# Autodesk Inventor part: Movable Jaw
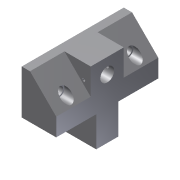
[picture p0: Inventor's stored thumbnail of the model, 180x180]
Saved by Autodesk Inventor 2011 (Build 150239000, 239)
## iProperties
Shininess: 77.0
Length Units: 11269
Angle Units: 11279
Time Units: 11290
Mass Units: 11283
Length Display Precision: 3
Angle Display Precision: 2
Created: 2002-02
Part Number: Movable Jaw
Document SubType Name: Modeling
Designer: ***
Density: 1 g/cm^3
Density: 0.0
Volumn: 0.0
Area: 0.0
PropertySet Name: Model Information
Control State: 0
Master: False
Checked Out: False
Author: ***
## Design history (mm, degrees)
sketch "Sketch2"
  geometry: L1 (2.39, 41.509)-(2.39, 9.509); L2 (2.39, 9.509)-(-22.61, 9.509); L3 (-22.61, 9.509)-(-22.61, 22.509); L4 (-22.61, 22.509)-(-3.61, 41.509); L5 (-3.61, 41.509)-(2.39, 41.509)
  constraints: 10 end point, 2 parallel, 1 perpendicular, 1 vertical
  dimensions: "d0" = 25 distance of L1.end L2.end; "d2" = 13 distance of L2.end L3.end; "d3" = 32 distance between parallel lines of L5 L2; "d4" = 6 distance of L4.end L1.start
extrude "Extrusion1" new body sketch "Sketch2" stored distance "d5" = 74; taper "d6" = 0 deg
sketch "Sketch3"
  geometry: L1 (-19, 25)-(11, 25); L2 (11, 25)-(11, 49); L3 (11, 49)-(-19, 49); L4 (-19, 49)-(-19, 25); L5 (0, 0)-(13, 0) reference; L6 (-19, 74)-(-19, 0) reference; L7 (11.924, 29)-(35, 29); L8 (35, 29)-(35, 45); L9 (35, 45)-(11.924, 45); L10 (11.924, 45)-(11.924, 29); L11 (13, 74)-(13, 0) reference
  constraints: 16 end point, 4 parallel, 2 horizontal, 2 perpendicular, 1 collinear
  dimensions: "d7" = 24 distance of L3.end L1.start; "d8" = 30 distance of L1.start L1.end; "d9" = 25 distance between parallel lines of L5 L1; "d10" = 16 distance of L7.end L8.end; "d11" = 4 distance between parallel lines of L3 L9; "d12" = 22 distance between parallel lines of L11 L8
extrude "Extrusion2" join sketch "Sketch3" distance "d13" = 25; taper "d14" = 0 deg
sketch "Sketch4"
  geometry: L1 (-19, -25)-(-19, -49) reference; L2 (-19, -49)-(0, -49) reference; 1 further point
  dimensions: "d15" = 11 distance from line of L1 point (-8, -37); "d16" = 12 distance from line of L2 point (-8, -37)
hole "Hole1" sketch "Sketch4" at (-8, -37) diameter "d17" = 10; stored, may be unused: countersink angle "d21" = 82 deg, drill point angle "d23" = 0 deg; dims "d18" = 6, "d19" = 4, "d20" = 2, "d22" = 13
sketch "Sketch5"
  geometry: L1 (-19, -49)-(-19, -74) reference; L2 (0, -74)-(13, -74) reference; 1 further point
  dimensions: "d24" = 14 distance from line of L1 point (-5, -62); "d25" = 12 distance from line of L2 point (-5, -62)
hole "Hole2" sketch "Sketch5" at (-5, -62) diameter "d26" = 6; stored, may be unused: countersink angle "d30" = 82 deg, drill point angle "d32" = 0 deg; dims "d27" = 6, "d28" = 8, "d29" = 10, "d31" = 13
mirror "Mirror1"
sketch "Sketch6"
  geometry: L1 (0, 19)-(0, 0) reference; 1 further point
  dimensions: "d33" = 5 distance from line of L1 point (-5, 8); "d34" = 11 vertical distance of L1.start point (-5, 8)
hole "Hole3" sketch "Sketch6" at (-5, 8) diameter "d35" = 2; stored, may be unused: countersink angle "d39" = 82 deg, drill point angle "d41" = 0 deg; dims "d36" = 6, "d37" = 8, "d38" = 10, "d40" = 13
body "Solid1"
